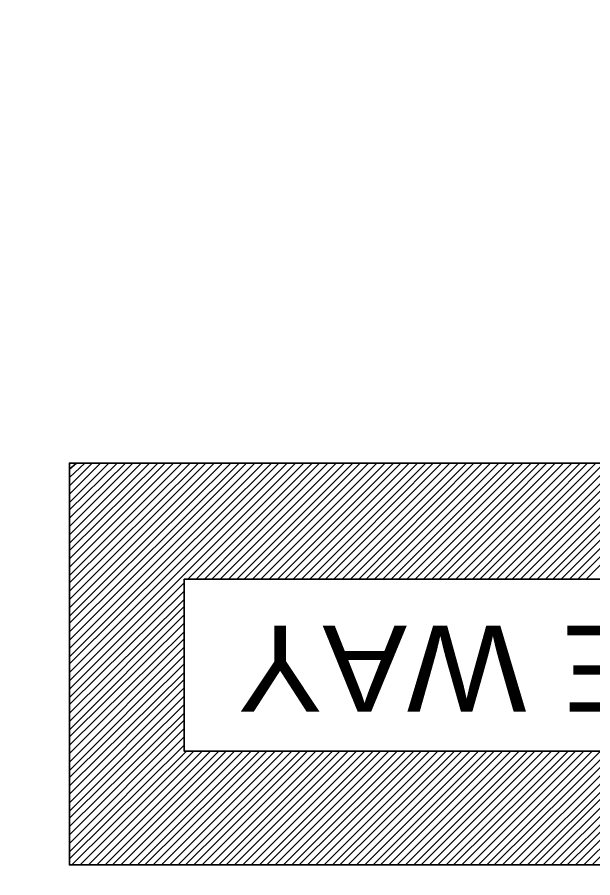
# Model space of a CAD drawing. Extents: x -133 to 547, y -328 to 112.
# Drawn here: x 416.4 to 426.02, y -138.32 to -123.93 of the extents above; entities that cross this region are included whole.
import ezdxf
from ezdxf.enums import TextEntityAlignment as Align

# ---------------------------------------------------------------- set-up
doc = ezdxf.new("R2010")
doc.units = 0
doc.header["$LTSCALE"] = 0.8
doc.layers.add('1', color=7, linetype='Continuous', lineweight=35)

msp = doc.modelspace()

# ---------------------------------------------------------------- linework, layer by layer
at = {"layer": '1'}
for p, q in [((421.0538, -131.3871), (417.2738, -135.1671)), ((420.9138, -131.3871), (417.2738, -135.0271)), ((420.7738, -131.3871), (417.2738, -134.8871)), ((420.6538, -131.3871), (417.2738, -134.7471)), ((420.5138, -131.3871), (417.2738, -134.6271)), ((420.3738, -131.3871), (417.2738, -134.4871)), ((420.2338, -131.3871), (417.2738, -134.3471)), ((420.1138, -131.3871), (417.2738, -134.2071)), ((419.9738, -131.3871), (417.2738, -134.0671)), ((419.8338, -131.3871), (417.2738, -133.9471)), ((419.6938, -131.3871), (417.2738, -133.8071)), ((419.5538, -131.3871), (417.2738, -133.6671)), ((419.4338, -131.3871), (417.2738, -133.5271)), ((419.2938, -131.3871), (417.2738, -133.3871)), ((419.1538, -131.3871), (417.2738, -133.2671)), ((419.0138, -131.3871), (417.2738, -133.1271)), ((418.8738, -131.3871), (417.2738, -132.9871)), ((418.7538, -131.3871), (417.2738, -132.8471)), ((418.6138, -131.3871), (417.2738, -132.7271)), ((418.4738, -131.3871), (417.2738, -132.5871)), ((418.3338, -131.3871), (417.2738, -132.4471)), ((418.2138, -131.3871), (417.2738, -132.3071)), ((418.0738, -131.3871), (417.2738, -132.1671)), ((417.9338, -131.3871), (417.2738, -132.0471)), ((417.7938, -131.3871), (417.2738, -131.9071)), ((417.6538, -131.3871), (417.2738, -131.7671)), ((417.5338, -131.3871), (417.2738, -131.6271)), ((417.3938, -131.3871), (417.2738, -131.4871)), ((421.0538, -131.3871), (417.2738, -135.1671)), ((420.9138, -131.3871), (417.2738, -135.0271)), ((420.7738, -131.3871), (417.2738, -134.8871)), ((420.6538, -131.3871), (417.2738, -134.7471)), ((420.5138, -131.3871), (417.2738, -134.6271)), ((420.3738, -131.3871), (417.2738, -134.4871)), ((420.2338, -131.3871), (417.2738, -134.3471)), ((420.1138, -131.3871), (417.2738, -134.2071)), ((419.9738, -131.3871), (417.2738, -134.0671)), ((419.8338, -131.3871), (417.2738, -133.9471)), ((419.6938, -131.3871), (417.2738, -133.8071)), ((419.5538, -131.3871), (417.2738, -133.6671)), ((419.4338, -131.3871), (417.2738, -133.5271)), ((419.2938, -131.3871), (417.2738, -133.3871)), ((419.1538, -131.3871), (417.2738, -133.2671)), ((419.0138, -131.3871), (417.2738, -133.1271)), ((418.8738, -131.3871), (417.2738, -132.9871)), ((418.7538, -131.3871), (417.2738, -132.8471)), ((418.6138, -131.3871), (417.2738, -132.7271)), ((418.4738, -131.3871), (417.2738, -132.5871)), ((418.3338, -131.3871), (417.2738, -132.4471)), ((418.2138, -131.3871), (417.2738, -132.3071)), ((418.0738, -131.3871), (417.2738, -132.1671)), ((417.9338, -131.3871), (417.2738, -132.0471)), ((417.7938, -131.3871), (417.2738, -131.9071)), ((417.6538, -131.3871), (417.2738, -131.7671)), ((417.5338, -131.3871), (417.2738, -131.6271)), ((417.3938, -131.3871), (417.2738, -131.4871)), ((421.1938, -131.3871), (419.2538, -133.3271)), ((421.1938, -131.3871), (419.2538, -133.3271)), ((421.3338, -131.3871), (419.3938, -133.3271)), ((421.3338, -131.3871), (419.3938, -133.3271)), ((421.4538, -131.3871), (419.5338, -133.3271)), ((421.4538, -131.3871), (419.5338, -133.3271)), ((421.5938, -131.3871), (419.6538, -133.3271)), ((421.5938, -131.3871), (419.6538, -133.3271)), ((421.7338, -131.3871), (419.7938, -133.3271)), ((421.7338, -131.3871), (419.7938, -133.3271)), ((421.8738, -131.3871), (419.9338, -133.3271)), ((421.8738, -131.3871), (419.9338, -133.3271)), ((422.0138, -131.3871), (420.0738, -133.3271)), ((422.0138, -131.3871), (420.0738, -133.3271)), ((422.1338, -131.3871), (420.1938, -133.3271)), ((422.1338, -131.3871), (420.1938, -133.3271)), ((422.2738, -131.3871), (420.3338, -133.3271)), ((422.2738, -131.3871), (420.3338, -133.3271)), ((422.4138, -131.3871), (420.4738, -133.3271)), ((422.4138, -131.3871), (420.4738, -133.3271)), ((422.5538, -131.3871), (420.6138, -133.3271)), ((422.5538, -131.3871), (420.6138, -133.3271)), ((422.6938, -131.3871), (420.7538, -133.3271)), ((422.6938, -131.3871), (420.7538, -133.3271)), ((422.8138, -131.3871), (420.8738, -133.3271)), ((422.8138, -131.3871), (420.8738, -133.3271)), ((422.9538, -131.3871), (421.0138, -133.3271)), ((422.9538, -131.3871), (421.0138, -133.3271)), ((423.0938, -131.3871), (421.1538, -133.3271)), ((423.0938, -131.3871), (421.1538, -133.3271)), ((423.2338, -131.3871), (421.2938, -133.3271)), ((423.2338, -131.3871), (421.2938, -133.3271)), ((423.3538, -131.3871), (421.4338, -133.3271)), ((423.3538, -131.3871), (421.4338, -133.3271)), ((423.4938, -131.3871), (421.5538, -133.3271)), ((423.4938, -131.3871), (421.5538, -133.3271)), ((423.6338, -131.3871), (421.6938, -133.3271)), ((423.6338, -131.3871), (421.6938, -133.3271)), ((423.7738, -131.3871), (421.8338, -133.3271)), ((423.7738, -131.3871), (421.8338, -133.3271)), ((423.9138, -131.3871), (421.9738, -133.3271)), ((423.9138, -131.3871), (421.9738, -133.3271)), ((424.0338, -131.3871), (422.1138, -133.3271)), ((424.0338, -131.3871), (422.1138, -133.3271)), ((424.1738, -131.3871), (422.2338, -133.3271)), ((424.1738, -131.3871), (422.2338, -133.3271)), ((424.3138, -131.3871), (422.3738, -133.3271)), ((424.3138, -131.3871), (422.3738, -133.3271)), ((424.4538, -131.3871), (422.5138, -133.3271)), ((424.4538, -131.3871), (422.5138, -133.3271)), ((424.5938, -131.3871), (422.6538, -133.3271)), ((424.5938, -131.3871), (422.6538, -133.3271)), ((424.7138, -131.3871), (422.7738, -133.3271)), ((424.7138, -131.3871), (422.7738, -133.3271)), ((424.8538, -131.3871), (422.9138, -133.3271)), ((424.8538, -131.3871), (422.9138, -133.3271)), ((424.9938, -131.3871), (423.0538, -133.3271)), ((424.9938, -131.3871), (423.0538, -133.3271)), ((425.1338, -131.3871), (423.1938, -133.3271)), ((425.1338, -131.3871), (423.1938, -133.3271)), ((425.2538, -131.3871), (423.3338, -133.3271)), ((425.2538, -131.3871), (423.3338, -133.3271)), ((425.3938, -131.3871), (423.4538, -133.3271)), ((425.3938, -131.3871), (423.4538, -133.3271)), ((425.5338, -131.3871), (423.5938, -133.3271)), ((425.5338, -131.3871), (423.5938, -133.3271)), ((425.6738, -131.3871), (423.7338, -133.3271)), ((425.6738, -131.3871), (423.7338, -133.3271)), ((425.8138, -131.3871), (423.8738, -133.3271)), ((425.8138, -131.3871), (423.8738, -133.3271)), ((425.9338, -131.3871), (424.0138, -133.3271)), ((425.9338, -131.3871), (424.0138, -133.3271)), ((426.0738, -131.3871), (424.1338, -133.3271)), ((426.0738, -131.3871), (424.1338, -133.3271)), ((426.2138, -131.3871), (424.2738, -133.3271)), ((426.2138, -131.3871), (424.2738, -133.3271)), ((426.3538, -131.3871), (424.4138, -133.3271)), ((426.3538, -131.3871), (424.4138, -133.3271)), ((426.4938, -131.3871), (424.5538, -133.3271)), ((426.4938, -131.3871), (424.5538, -133.3271)), ((426.6138, -131.3871), (424.6738, -133.3271)), ((426.6138, -131.3871), (424.6738, -133.3271)), ((426.7538, -131.3871), (424.8138, -133.3271)), ((426.7538, -131.3871), (424.8138, -133.3271)), ((426.8938, -131.3871), (424.9538, -133.3271)), ((426.8938, -131.3871), (424.9538, -133.3271)), ((427.0338, -131.3871), (425.0938, -133.3271)), ((427.0338, -131.3871), (425.0938, -133.3271)), ((427.1738, -131.3871), (425.2338, -133.3271)), ((427.1738, -131.3871), (425.2338, -133.3271)), ((427.2938, -131.3871), (425.3538, -133.3271)), ((427.2938, -131.3871), (425.3538, -133.3271)), ((427.4338, -131.3871), (425.4938, -133.3271)), ((427.4338, -131.3871), (425.4938, -133.3271)), ((427.5738, -131.3871), (425.6338, -133.3271)), ((427.5738, -131.3871), (425.6338, -133.3271)), ((427.7138, -131.3871), (425.7738, -133.3271)), ((427.7138, -131.3871), (425.7738, -133.3271)), ((427.8338, -131.3871), (425.9138, -133.3271)), ((427.8338, -131.3871), (425.9138, -133.3271)), ((419.1938, -133.3871), (417.2738, -135.3071)), ((419.1938, -133.3871), (417.2738, -135.3071)), ((419.1938, -133.5271), (417.2738, -135.4271)), ((419.1938, -133.5271), (417.2738, -135.4271)), ((419.1938, -133.6671), (417.2738, -135.5671)), ((419.1938, -133.6671), (417.2738, -135.5671)), ((419.1938, -133.7871), (417.2738, -135.7071)), ((419.1938, -133.7871), (417.2738, -135.7071)), ((419.1938, -133.9271), (417.2738, -135.8471)), ((419.1938, -133.9271), (417.2738, -135.8471)), ((419.1938, -134.0671), (417.2738, -135.9671)), ((419.1938, -134.0671), (417.2738, -135.9671)), ((419.1938, -134.2071), (417.2738, -136.1071)), ((419.1938, -134.2071), (417.2738, -136.1071)), ((419.1938, -134.3271), (417.2738, -136.2471)), ((419.1938, -134.3271), (417.2738, -136.2471)), ((419.1938, -134.4671), (417.2738, -136.3871)), ((419.1938, -134.4671), (417.2738, -136.3871)), ((419.1938, -134.6071), (417.2738, -136.5271)), ((419.1938, -134.6071), (417.2738, -136.5271)), ((419.1938, -134.7471), (417.2738, -136.6471)), ((419.1938, -134.7471), (417.2738, -136.6471)), ((419.1938, -134.8871), (417.2738, -136.7871)), ((419.1938, -134.8871), (417.2738, -136.7871)), ((419.1938, -135.0071), (417.2738, -136.9271)), ((419.1938, -135.0071), (417.2738, -136.9271)), ((419.1938, -135.1471), (417.2738, -137.0671)), ((419.1938, -135.1471), (417.2738, -137.0671)), ((419.1938, -135.2871), (417.2738, -137.2071)), ((419.1938, -135.2871), (417.2738, -137.2071)), ((419.1938, -135.4271), (417.2738, -137.3271)), ((419.1938, -135.4271), (417.2738, -137.3271)), ((419.1938, -135.5671), (417.2738, -137.4671)), ((419.1938, -135.5671), (417.2738, -137.4671)), ((419.1938, -135.6871), (417.2738, -137.6071)), ((419.1938, -135.6871), (417.2738, -137.6071)), ((419.1938, -135.8271), (417.2738, -137.7471)), ((419.1938, -135.8271), (417.2738, -137.7471)), ((419.1938, -135.9671), (417.2738, -137.8871)), ((419.1938, -135.9671), (417.2738, -137.8871)), ((419.1938, -136.1071), (417.2738, -138.0071)), ((419.1938, -136.1071), (417.2738, -138.0071)), ((419.2338, -136.2071), (417.3138, -138.1071)), ((419.2338, -136.2071), (417.3138, -138.1071)), ((419.3538, -136.2071), (417.4538, -138.1071)), ((419.3538, -136.2071), (417.4538, -138.1071)), ((419.4938, -136.2071), (417.5938, -138.1071)), ((419.4938, -136.2071), (417.5938, -138.1071)), ((419.6338, -136.2071), (417.7338, -138.1071)), ((419.6338, -136.2071), (417.7338, -138.1071)), ((419.7738, -136.2071), (417.8738, -138.1071)), ((419.7738, -136.2071), (417.8738, -138.1071)), ((419.8938, -136.2071), (417.9938, -138.1071)), ((419.8938, -136.2071), (417.9938, -138.1071)), ((420.0338, -136.2071), (418.1338, -138.1071)), ((420.0338, -136.2071), (418.1338, -138.1071)), ((420.1738, -136.2071), (418.2738, -138.1071)), ((420.1738, -136.2071), (418.2738, -138.1071)), ((420.3138, -136.2071), (418.4138, -138.1071)), ((420.3138, -136.2071), (418.4138, -138.1071)), ((420.4538, -136.2071), (418.5338, -138.1071)), ((420.4538, -136.2071), (418.5338, -138.1071)), ((420.5738, -136.2071), (418.6738, -138.1071)), ((420.5738, -136.2071), (418.6738, -138.1071)), ((420.7138, -136.2071), (418.8138, -138.1071)), ((420.7138, -136.2071), (418.8138, -138.1071)), ((420.8538, -136.2071), (418.9538, -138.1071)), ((420.8538, -136.2071), (418.9538, -138.1071)), ((420.9938, -136.2071), (419.0938, -138.1071)), ((420.9938, -136.2071), (419.0938, -138.1071)), ((421.1338, -136.2071), (419.2138, -138.1071)), ((421.1338, -136.2071), (419.2138, -138.1071)), ((421.2538, -136.2071), (419.3538, -138.1071)), ((421.2538, -136.2071), (419.3538, -138.1071)), ((421.3938, -136.2071), (419.4938, -138.1071)), ((421.3938, -136.2071), (419.4938, -138.1071)), ((421.5338, -136.2071), (419.6338, -138.1071)), ((421.5338, -136.2071), (419.6338, -138.1071)), ((421.6738, -136.2071), (419.7738, -138.1071)), ((421.6738, -136.2071), (419.7738, -138.1071)), ((421.7938, -136.2071), (419.8938, -138.1071)), ((421.7938, -136.2071), (419.8938, -138.1071)), ((421.9338, -136.2071), (420.0338, -138.1071)), ((421.9338, -136.2071), (420.0338, -138.1071)), ((422.0738, -136.2071), (420.1738, -138.1071)), ((422.0738, -136.2071), (420.1738, -138.1071)), ((422.2138, -136.2071), (420.3138, -138.1071)), ((422.2138, -136.2071), (420.3138, -138.1071)), ((422.3538, -136.2071), (420.4538, -138.1071)), ((422.3538, -136.2071), (420.4538, -138.1071)), ((422.4738, -136.2071), (420.5738, -138.1071)), ((422.4738, -136.2071), (420.5738, -138.1071)), ((422.6138, -136.2071), (420.7138, -138.1071)), ((422.6138, -136.2071), (420.7138, -138.1071)), ((422.7538, -136.2071), (420.8538, -138.1071)), ((422.7538, -136.2071), (420.8538, -138.1071)), ((422.8938, -136.2071), (420.9938, -138.1071)), ((422.8938, -136.2071), (420.9938, -138.1071)), ((423.0338, -136.2071), (421.1138, -138.1071)), ((423.0338, -136.2071), (421.1138, -138.1071)), ((423.1538, -136.2071), (421.2538, -138.1071)), ((423.1538, -136.2071), (421.2538, -138.1071)), ((423.2938, -136.2071), (421.3938, -138.1071)), ((423.2938, -136.2071), (421.3938, -138.1071)), ((423.4338, -136.2071), (421.5338, -138.1071)), ((423.4338, -136.2071), (421.5338, -138.1071)), ((423.5738, -136.2071), (421.6738, -138.1071)), ((423.5738, -136.2071), (421.6738, -138.1071)), ((423.7138, -136.2071), (421.7938, -138.1071)), ((423.7138, -136.2071), (421.7938, -138.1071)), ((423.8338, -136.2071), (421.9338, -138.1071)), ((423.8338, -136.2071), (421.9338, -138.1071)), ((423.9738, -136.2071), (422.0738, -138.1071)), ((423.9738, -136.2071), (422.0738, -138.1071)), ((424.1138, -136.2071), (422.2138, -138.1071)), ((424.1138, -136.2071), (422.2138, -138.1071)), ((424.2538, -136.2071), (422.3538, -138.1071)), ((424.2538, -136.2071), (422.3538, -138.1071)), ((424.3738, -136.2071), (422.4738, -138.1071)), ((424.3738, -136.2071), (422.4738, -138.1071)), ((424.5138, -136.2071), (422.6138, -138.1071)), ((424.5138, -136.2071), (422.6138, -138.1071)), ((424.6538, -136.2071), (422.7538, -138.1071)), ((424.6538, -136.2071), (422.7538, -138.1071)), ((424.7938, -136.2071), (422.8938, -138.1071)), ((424.7938, -136.2071), (422.8938, -138.1071)), ((424.9338, -136.2071), (423.0338, -138.1071)), ((424.9338, -136.2071), (423.0338, -138.1071)), ((425.0538, -136.2071), (423.1538, -138.1071)), ((425.0538, -136.2071), (423.1538, -138.1071)), ((425.1938, -136.2071), (423.2938, -138.1071)), ((425.1938, -136.2071), (423.2938, -138.1071)), ((425.3338, -136.2071), (423.4338, -138.1071)), ((425.3338, -136.2071), (423.4338, -138.1071)), ((425.4738, -136.2071), (423.5738, -138.1071)), ((425.4738, -136.2071), (423.5738, -138.1071)), ((425.6138, -136.2071), (423.6938, -138.1071)), ((425.6138, -136.2071), (423.6938, -138.1071)), ((425.7338, -136.2071), (423.8338, -138.1071)), ((425.7338, -136.2071), (423.8338, -138.1071)), ((425.8738, -136.2071), (423.9738, -138.1071)), ((425.8738, -136.2071), (423.9738, -138.1071)), ((426.0138, -136.2071), (424.1138, -138.1071)), ((426.0138, -136.2071), (424.1138, -138.1071)), ((426.1538, -136.2071), (424.2538, -138.1071)), ((426.1538, -136.2071), (424.2538, -138.1071)), ((426.2938, -136.2071), (424.3738, -138.1071)), ((426.2938, -136.2071), (424.3738, -138.1071)), ((426.4138, -136.2071), (424.5138, -138.1071)), ((426.4138, -136.2071), (424.5138, -138.1071)), ((426.5538, -136.2071), (424.6538, -138.1071)), ((426.5538, -136.2071), (424.6538, -138.1071)), ((426.6938, -136.2071), (424.7938, -138.1071)), ((426.6938, -136.2071), (424.7938, -138.1071)), ((426.8338, -136.2071), (424.9338, -138.1071)), ((426.8338, -136.2071), (424.9338, -138.1071)), ((426.9538, -136.2071), (425.0538, -138.1071)), ((426.9538, -136.2071), (425.0538, -138.1071)), ((427.0938, -136.2071), (425.1938, -138.1071)), ((427.0938, -136.2071), (425.1938, -138.1071)), ((427.2338, -136.2071), (425.3338, -138.1071)), ((427.2338, -136.2071), (425.3338, -138.1071)), ((427.3738, -136.2071), (425.4738, -138.1071)), ((427.3738, -136.2071), (425.4738, -138.1071)), ((427.5138, -136.2071), (425.5938, -138.1071)), ((427.5138, -136.2071), (425.5938, -138.1071)), ((427.6338, -136.2071), (425.7338, -138.1071)), ((427.6338, -136.2071), (425.7338, -138.1071)), ((427.7738, -136.2071), (425.8738, -138.1071)), ((427.7738, -136.2071), (425.8738, -138.1071)), ((427.9138, -136.2071), (426.0138, -138.1071)), ((427.9138, -136.2071), (426.0138, -138.1071))]:
    msp.add_line(p, q, dxfattribs=at)
msp.add_lwpolyline([(435.5138, -138.1071), (417.2738, -138.1071), (417.2738, -131.3871), (435.5138, -131.3871)], close=True, dxfattribs=at)
msp.add_lwpolyline([(435.5138, -138.1071), (417.2738, -138.1071), (417.2738, -131.3871), (435.5138, -131.3871)], close=True, dxfattribs=at)
msp.add_lwpolyline([(430.6138, -137.1471), (430.7138, -136.2071), (419.1938, -136.2071), (419.1938, -133.3271), (430.7138, -133.3271), (430.6138, -132.3671)], dxfattribs=at)
msp.add_lwpolyline([(430.6138, -137.1471), (430.7138, -136.2071), (419.1938, -136.2071), (419.1938, -133.3271), (430.7138, -133.3271), (430.6138, -132.3671)], dxfattribs=at)
at = {"layer": '1', "lineweight": 53}
msp.add_arc((422.8289, -169.145), 50, 90, 180, dxfattribs=at)

# ---------------------------------------------------------------- texts
at = {"layer": '1', "width": 1.1}
msp.add_text('ONE WAY', height=1.44, rotation=180, dxfattribs=at).set_placement((425.0935, -134.1071), align=Align.CENTER)
msp.add_text('ONE WAY', height=1.44, rotation=180, dxfattribs=at).set_placement((425.0935, -134.1071), align=Align.CENTER)

doc.saveas('drawing.dxf')
